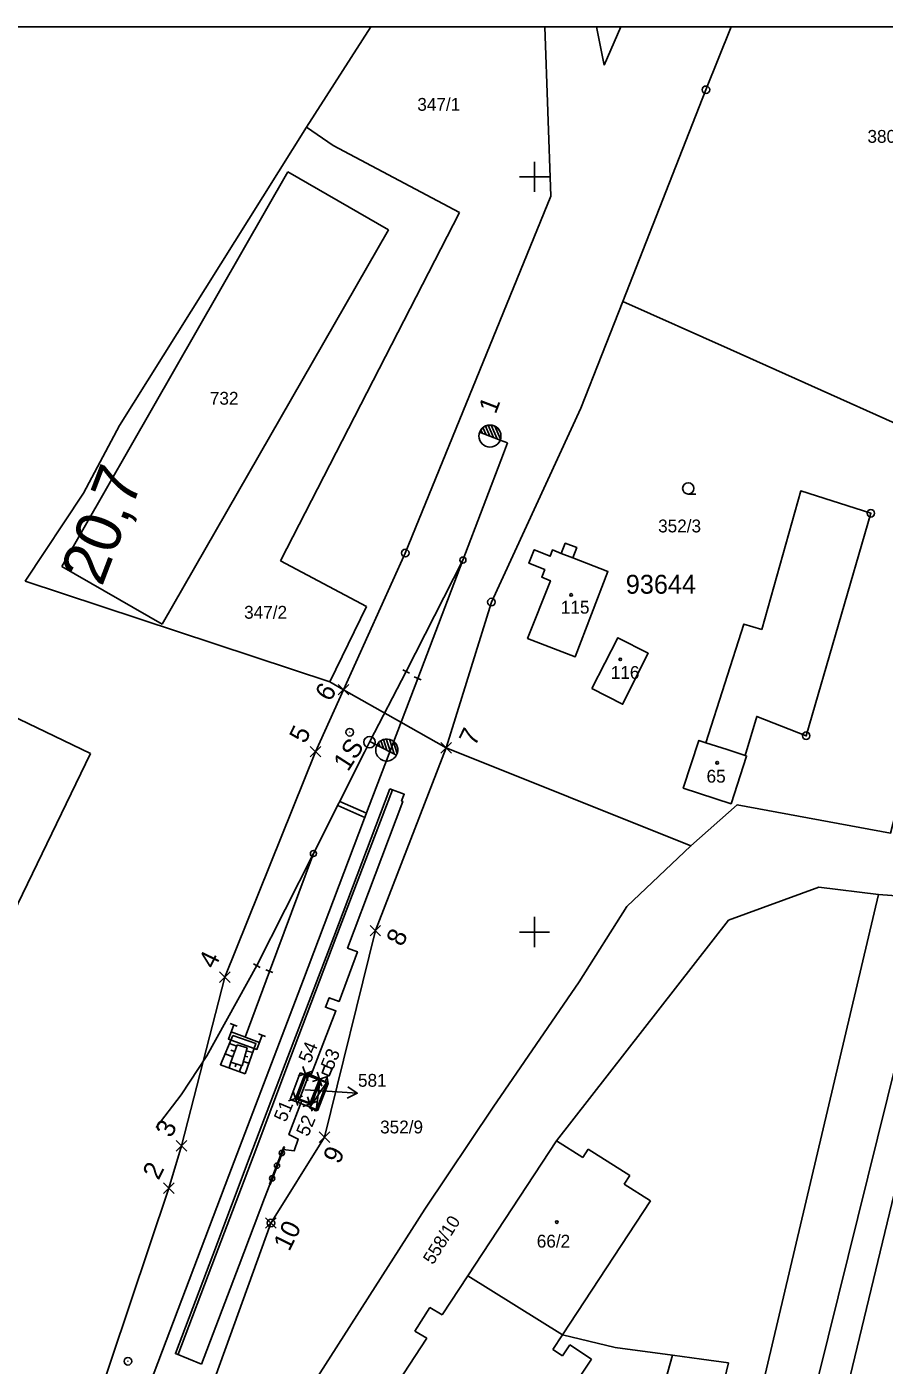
# Model space of a CAD drawing. Extents: x -778045 to -768365, y -1202571 to -1202059.
# Drawn here: x -777867.3 to -777753.6, y -1202457.4 to -1202280.1 of the extents above; entities that cross this region are included whole.
import ezdxf

# ---------------------------------------------------------------- set-up
doc = ezdxf.new("R2010")
doc.units = 0
for name, color, linetype in [('BPEJ', 7, 'Continuous'), ('GD_Demolice', 7, 'Continuous'), ('GD_Nový stav', 7, 'Continuous'), ('GD_Starý stav', 7, 'Continuous'), ('Groma (60)', 7, 'Continuous'), ('Katastr_HRANICE DRÁHY', 7, 'Continuous'), ('Katastr_Hranice katastrální', 7, 'Continuous'), ('Katastr_Hranice parcel', 7, 'Continuous'), ('Katastr_Parcelní čísla', 7, 'Continuous'), ('Katastr_Slučkované čáry', 7, 'Continuous'), ('Katastr_Značky kultur', 7, 'Continuous'), ('Vrstva 7', 7, 'Continuous'), ('čtvercová síť', 7, 'Continuous')]:
    doc.layers.add(name, color=color, linetype=linetype)

# ---------------------------------------------------------------- blocks, each defined once
blk = doc.blocks.new('POINT_DISPLAY')
for p, q in [((-0.7, -0.7), (0.7, 0.7)), ((-0.7, 0.7), (0.7, -0.7))]:
    blk.add_line(p, q)
blk = doc.blocks.new('C691')
at = {"layer": 'čtvercová síť'}
for p, q in [((0, 0.5), (0, -0.5)), ((-0.5, 0), (0.5, 0))]:
    blk.add_line(p, q, dxfattribs=at)

msp = doc.modelspace()

# ---------------------------------------------------------------- linework, layer by layer
at = {"layer": 'BPEJ'}
for points in [[(-777788.3, -1202316.49), (-777774.01, -1202322.88), (-777740.14, -1202338.03), (-777752.8, -1202386.89), (-777773.14, -1202383.15), (-777779.27, -1202388.61), (-777811.7, -1202375.6), (-777805.7, -1202356.3), (-777793.87, -1202330.63), (-777788.3, -1202316.49)], [(-777769.85, -1202359.94), (-777764.72, -1202341.59), (-777755.42, -1202344.55), (-777763.99, -1202374), (-777770.53, -1202371.45), (-777772.08, -1202376.64), (-777771.88, -1202376.7), (-777773.95, -1202383.02), (-777780.27, -1202380.95), (-777778.2, -1202374.63), (-777777.29, -1202374.93), (-777772.26, -1202359.22), (-777769.85, -1202359.94)], [(-777796.44, -1202349.87), (-777795.91, -1202348.51), (-777794.39, -1202349.09), (-777794.91, -1202350.46), (-777790.27, -1202352.24), (-777794.6, -1202363.54), (-777800.91, -1202361.12), (-777797.88, -1202353.49), (-777799.04, -1202353.02), (-777798.64, -1202352), (-777800.73, -1202351.17), (-777800.03, -1202349.39), (-777797.93, -1202350.23), (-777797.61, -1202349.41), (-777796.44, -1202349.87)], [(-777792.39, -1202367.77), (-777788.94, -1202361.03), (-777784.91, -1202363.08), (-777788.31, -1202369.84), (-777792.39, -1202367.77)]]:
    msp.add_lwpolyline(points, dxfattribs=at)
at = {"layer": 'Defpoints'}
msp.add_line((-777624.79, -1202280.12), (-778044.79, -1202280.12), dxfattribs=at)
at = {"layer": 'GD_Demolice'}
for points in [[(-777829.5, -1202422.72), (-777831.43, -1202422.03), (-777830.16, -1202418.71)], [(-777830.16, -1202418.71), (-777828.31, -1202419.48), (-777829.5, -1202422.72)]]:
    msp.add_lwpolyline(points, dxfattribs=at)
at = {"layer": 'GD_Nový stav'}
for p, q in [((-777831.04, -1202418.63), (-777832.39, -1202422.18)), ((-777831.04, -1202418.63), (-777829.96, -1202419.04)), ((-777827.5, -1202419.87), (-777829.8, -1202423.27)), ((-777829.77, -1202423.18), (-777828.42, -1202419.63)), ((-777828.38, -1202419.53), (-777828.92, -1202423.61)), ((-777832.39, -1202422.18), (-777831.31, -1202422.59))]:
    msp.add_line(p, q, dxfattribs=at)
for points in [[(-777827.76, -1202417.74), (-777826.82, -1202418.09), (-777827.18, -1202419.03), (-777828.11, -1202418.67)], [(-777829.96, -1202419.04), (-777827.53, -1202419.96), (-777828.88, -1202423.52), (-777831.31, -1202422.59)]]:
    msp.add_lwpolyline(points, close=True, dxfattribs=at)
for points in [[(-777829.12, -1202423.53), (-777829.16, -1202423.63), (-777828.95, -1202423.7), (-777828.69, -1202423.59), (-777827.34, -1202420.04), (-777827.47, -1202419.25)], [(-777828.42, -1202419.63), (-777828.38, -1202419.53), (-777827.5, -1202419.87), (-777827.53, -1202419.96)], [(-777827.68, -1202419.8), (-777827.36, -1202418.96)], [(-777829.77, -1202423.18), (-777829.8, -1202423.27), (-777828.92, -1202423.61), (-777828.88, -1202423.52)], [(-777833.12, -1202428.48), (-777833.22, -1202428.45), (-777835.1, -1202433.4), (-777835.01, -1202433.44), (-777833.12, -1202428.48)]]:
    msp.add_lwpolyline(points, dxfattribs=at)
for centre in [(-777833.47, -1202429.26), (-777834.11, -1202430.94), (-777834.75, -1202432.63)]:
    msp.add_circle(centre, 0.35, dxfattribs=at)
at = {"layer": 'GD_Starý stav'}
for p, q in [((-777806.9, -1202333.95), (-777807.1, -1202333.51)), ((-777806.41, -1202334.14), (-777806.82, -1202333.21)), ((-777805.91, -1202334.33), (-777806.5, -1202333.01)), ((-777805.41, -1202334.52), (-777806.14, -1202332.9)), ((-777804.92, -1202334.71), (-777805.74, -1202332.88)), ((-777804.49, -1202334.75), (-777805.26, -1202333.02)), ((-777804.52, -1202334.86), (-777803.56, -1202335.22)), ((-777809.48, -1202350.75), (-777816.98, -1202365.49)), ((-777816.98, -1202365.49), (-777809.48, -1202350.75)), ((-777816.98, -1202365.49), (-777821.8, -1202374.78)), ((-777816.54, -1202365.72), (-777817.42, -1202365.26)), ((-777814.99, -1202366.59), (-777815.92, -1202366.23)), ((-777820, -1202374.51), (-777819.54, -1202375.92)), ((-777819.63, -1202374.44), (-777819.06, -1202376.16)), ((-777819.21, -1202374.48), (-777818.58, -1202376.4)), ((-777822.51, -1202376.18), (-777829.29, -1202389.61)), ((-777822.51, -1202376.18), (-777829.29, -1202389.61)), ((-777821.8, -1202374.78), (-777822.51, -1202376.18)), ((-777821.8, -1202374.78), (-777822.51, -1202376.18)), ((-777820.87, -1202375.24), (-777821.8, -1202374.78)), ((-777820.66, -1202374.94), (-777820.5, -1202375.43)), ((-777820.35, -1202374.67), (-777820.02, -1202375.67)), ((-777818.74, -1202374.69), (-777818.18, -1202376.37)), ((-777826.07, -1202383.23), (-777822.47, -1202384.82)), ((-777825.8, -1202382.7), (-777822.26, -1202384.26)), ((-777829.29, -1202389.61), (-777836.79, -1202404.45)), ((-777829.29, -1202389.61), (-777836.79, -1202404.45)), ((-777829.29, -1202389.61), (-777835.12, -1202405.21)), ((-777829.29, -1202389.61), (-777835.12, -1202405.21)), ((-777836.35, -1202404.69), (-777837.23, -1202404.21)), ((-777835.12, -1202405.21), (-777838.32, -1202413.93)), ((-777834.65, -1202405.38), (-777835.59, -1202405.03)), ((-777839.38, -1202412.47), (-777840.32, -1202412.13)), ((-777836.44, -1202414.61), (-777840.2, -1202413.24)), ((-777835.63, -1202413.85), (-777836.57, -1202413.5)), ((-777839.45, -1202415.13), (-777840.42, -1202414.76)), ((-777839.98, -1202416.53), (-777841, -1202416.14)), ((-777839.71, -1202415.83), (-777840.21, -1202415.64)), ((-777838.38, -1202416.44), (-777837.98, -1202416.55)), ((-777838.18, -1202415.72), (-777837.33, -1202415.96)), ((-777840.22, -1202417.24), (-777840.47, -1202417.99)), ((-777839.51, -1202417.47), (-777839.64, -1202417.86)), ((-777838.8, -1202417.71), (-777839.06, -1202418.49)), ((-777838.59, -1202417.16), (-777837.83, -1202417.38))]:
    msp.add_line(p, q, dxfattribs=at)
for points in [[(-777803.56, -1202335.22), (-777804.09, -1202336.62), (-777809.48, -1202350.75), (-777815.46, -1202366.41)], [(-777815.46, -1202366.41), (-777809.48, -1202350.75), (-777804.09, -1202336.62), (-777803.56, -1202335.22)], [(-777804.52, -1202334.86), (-777807.26, -1202333.81)], [(-777804.52, -1202334.86), (-777804.52, -1202334.86)], [(-777865.08, -1202504.23), (-777861.67, -1202489.74), (-777857.48, -1202477.13), (-777850.38, -1202458.32), (-777840.49, -1202432.25), (-777830.62, -1202406.28), (-777821.88, -1202383.27), (-777815.46, -1202366.41)], [(-777818.26, -1202376.56), (-777820.87, -1202375.24)], [(-777818.26, -1202376.56), (-777818.26, -1202376.56)], [(-777844.11, -1202457.24), (-777847.57, -1202455.83), (-777842.63, -1202442.78), (-777837.65, -1202429.62), (-777832.66, -1202416.55), (-777826.6, -1202400.65), (-777819.16, -1202381.05)], [(-777847.25, -1202456.03), (-777842.26, -1202442.89), (-777837.28, -1202429.79), (-777832.33, -1202416.64), (-777826.31, -1202400.77), (-777818.81, -1202381.19), (-777818.81, -1202381.2)], [(-777844.11, -1202457.24), (-777839.11, -1202444.1), (-777835.76, -1202435.24), (-777834.05, -1202430.85), (-777833.28, -1202428.8), (-777831.86, -1202428.99), (-777831.3, -1202427.43), (-777832.54, -1202426.83), (-777830.84, -1202422.31), (-777831.43, -1202422.03), (-777830.16, -1202418.71), (-777829.52, -1202418.79), (-777826.31, -1202410.46), (-777827.69, -1202409.96), (-777827.2, -1202408.71), (-777825.88, -1202409.2), (-777823.46, -1202402.62), (-777824.77, -1202402.13), (-777817.44, -1202382.7), (-777817.6, -1202382.63), (-777817.25, -1202381.75), (-777819.16, -1202381.05)], [(-777836.79, -1202404.45), (-777843.41, -1202416.39), (-777846.83, -1202421.54)], [(-777839.85, -1202412.3), (-777840.54, -1202414.18), (-777836.78, -1202415.55), (-777836.1, -1202413.68)], [(-777838.32, -1202418.76), (-777841.61, -1202417.58), (-777839.97, -1202413.69)], [(-777838.75, -1202417.73), (-777840.24, -1202417.23), (-777839.38, -1202414.96)], [(-777839.97, -1202413.69), (-777836.9, -1202414.75), (-777838.32, -1202418.76)], [(-777839.38, -1202414.96), (-777838.07, -1202415.32), (-777838.75, -1202417.73)], [(-777850.13, -1202425.87), (-777846.83, -1202421.54)]]:
    msp.add_lwpolyline(points, dxfattribs=at)
for centre, radius in [((-777805.9, -1202334.33), 1.46), ((-777809.48, -1202350.75), 0.4), ((-777829.29, -1202389.61), 0.4)]:
    msp.add_circle(centre, radius, dxfattribs=at)
for centre, start, end in [((-777805.89, -1202334.34), 339.1309, 159.0918), ((-777819.57, -1202375.9), 333.368, 153.3289), ((-777819.57, -1202375.9), 153.2834, 333.7529)]:
    msp.add_arc(centre, 1.46, start, end, dxfattribs=at)
at = {"layer": 'Katastr_HRANICE DRÁHY'}
for points in [[(-777798.62, -1202280.12), (-777797.84, -1202302.55)], [(-777791.78, -1202280.12), (-777790.77, -1202285.22)], [(-777790.77, -1202285.22), (-777788.57, -1202280.12)], [(-777777.27, -1202288.47), (-777773.95, -1202280.12)], [(-777788.3, -1202316.49), (-777777.27, -1202288.47)], [(-777817.11, -1202349.82), (-777797.84, -1202302.55)], [(-777788.3, -1202316.49), (-777793.87, -1202330.63)], [(-777805.7, -1202356.3), (-777793.87, -1202330.63)], [(-777817.11, -1202349.82), (-777825.29, -1202367.91)], [(-777805.7, -1202356.3), (-777811.7, -1202375.6)], [(-777825.29, -1202367.91), (-777829.01, -1202376.12)], [(-777841.03, -1202405.98), (-777829.01, -1202376.12)], [(-777811.7, -1202375.6), (-777821.08, -1202399.82)], [(-777821.08, -1202399.82), (-777827.81, -1202427.16)], [(-777846.76, -1202428.33), (-777841.03, -1202405.98)], [(-777827.81, -1202427.16), (-777834.92, -1202438.54)], [(-777848.44, -1202433.92), (-777846.76, -1202428.33)], [(-777863.81, -1202479.74), (-777848.44, -1202433.92)], [(-777834.92, -1202438.54), (-777859.87, -1202507.59)]]:
    msp.add_lwpolyline(points, dxfattribs=at)
at = {"layer": 'Katastr_Hranice katastrální'}
for points in [[(-777830.2, -1202293.41), (-777821.68, -1202280.12)], [(-777854.99, -1202332.94), (-777830.2, -1202293.41)], [(-777859.77, -1202341.9), (-777854.99, -1202332.94)], [(-777867.47, -1202353.53), (-777859.77, -1202341.9)]]:
    msp.add_lwpolyline(points, dxfattribs=at)
at = {"layer": 'Katastr_Hranice parcel'}
msp.add_line((-777750.49, -1202426.97), (-777772.39, -1202517.89), dxfattribs=at)
for points in [[(-777830.2, -1202293.41), (-777826.67, -1202295.84)], [(-777826.67, -1202295.84), (-777809.94, -1202304.72)], [(-777832.67, -1202299.35), (-777862.62, -1202351.59)], [(-777819.32, -1202307.02), (-777832.67, -1202299.35)], [(-777809.94, -1202304.72), (-777833.64, -1202350.84)], [(-777849.34, -1202359.23), (-777819.32, -1202307.02)], [(-777788.3, -1202316.49), (-777774.01, -1202322.88)], [(-777774.01, -1202322.88), (-777740.14, -1202338.03)], [(-777769.85, -1202359.94), (-777764.72, -1202341.59)], [(-777755.42, -1202344.55), (-777764.72, -1202341.59)], [(-777755.42, -1202344.55), (-777763.99, -1202374)], [(-777800.03, -1202349.39), (-777800.73, -1202351.17)], [(-777797.93, -1202350.23), (-777800.03, -1202349.39)], [(-777797.61, -1202349.41), (-777797.93, -1202350.23)], [(-777796.44, -1202349.87), (-777797.61, -1202349.41)], [(-777795.91, -1202348.51), (-777796.44, -1202349.87)], [(-777794.39, -1202349.09), (-777795.91, -1202348.51)], [(-777794.91, -1202350.46), (-777794.39, -1202349.09)], [(-777833.64, -1202350.84), (-777822.24, -1202356.89)], [(-777800.73, -1202351.17), (-777798.64, -1202352)], [(-777790.27, -1202352.24), (-777794.91, -1202350.46)], [(-777862.62, -1202351.59), (-777849.34, -1202359.23)], [(-777798.64, -1202352), (-777799.04, -1202353.02)], [(-777799.04, -1202353.02), (-777797.88, -1202353.49)], [(-777794.6, -1202363.54), (-777790.27, -1202352.24)], [(-777827.09, -1202366.89), (-777867.47, -1202353.53)], [(-777797.88, -1202353.49), (-777800.91, -1202361.12)], [(-777822.24, -1202356.89), (-777827.09, -1202366.89)], [(-777777.29, -1202374.93), (-777772.26, -1202359.22)], [(-777769.85, -1202359.94), (-777772.26, -1202359.22)], [(-777794.6, -1202363.54), (-777800.91, -1202361.12)], [(-777792.39, -1202367.77), (-777788.94, -1202361.03)], [(-777788.94, -1202361.03), (-777784.91, -1202363.08)], [(-777784.91, -1202363.08), (-777788.31, -1202369.84)], [(-777825.29, -1202367.91), (-777827.09, -1202366.89)], [(-777825.29, -1202367.91), (-777817.69, -1202372.21)], [(-777788.31, -1202369.84), (-777792.39, -1202367.77)], [(-777858.82, -1202376.38), (-777873.08, -1202369.51)], [(-777817.69, -1202372.21), (-777811.7, -1202375.6)], [(-777770.53, -1202371.45), (-777772.08, -1202376.64)], [(-777770.53, -1202371.45), (-777763.99, -1202374)], [(-777811.7, -1202375.6), (-777779.27, -1202388.61)], [(-777780.27, -1202380.95), (-777778.2, -1202374.63)], [(-777778.2, -1202374.63), (-777777.29, -1202374.93)], [(-777882.63, -1202425.49), (-777858.82, -1202376.38)], [(-777771.88, -1202376.7), (-777773.95, -1202383.02)], [(-777772.08, -1202376.64), (-777771.88, -1202376.7)], [(-777773.95, -1202383.02), (-777780.27, -1202380.95)], [(-777773.14, -1202383.15), (-777779.27, -1202388.61)], [(-777752.8, -1202386.89), (-777773.14, -1202383.15)], [(-777779.27, -1202388.61), (-777787.77, -1202396.63)], [(-777746.67, -1202395.6), (-777776.75, -1202516.88)], [(-777754.4, -1202395.04), (-777775.07, -1202482.53)], [(-777762.31, -1202394.08), (-777774.3, -1202398.44)], [(-777754.4, -1202395.04), (-777762.31, -1202394.08)], [(-777754.4, -1202395.04), (-777746.67, -1202395.6)], [(-777787.77, -1202396.63), (-777794.06, -1202406.58)], [(-777774.3, -1202398.44), (-777797.09, -1202427.66)], [(-777794.06, -1202406.58), (-777805.47, -1202423.21)], [(-777830.36, -1202418.75), (-777831.65, -1202422.04)], [(-777828.47, -1202419.49), (-777830.36, -1202418.75)], [(-777829.76, -1202422.77), (-777828.47, -1202419.49)], [(-777831.65, -1202422.04), (-777829.76, -1202422.77)], [(-777805.47, -1202423.21), (-777814.54, -1202436.71)], [(-777808.84, -1202445.53), (-777797.09, -1202427.66)], [(-777797.09, -1202427.66), (-777793.6, -1202429.88)], [(-777793.6, -1202429.88), (-777792.87, -1202428.75)], [(-777792.87, -1202428.75), (-777787.37, -1202432.25)], [(-777787.37, -1202432.25), (-777788.1, -1202433.39)], [(-777788.1, -1202433.39), (-777784.62, -1202435.6)], [(-777784.62, -1202435.6), (-777796.28, -1202453.34)], [(-777814.54, -1202436.71), (-777859.87, -1202507.59)], [(-777812.23, -1202450.69), (-777808.84, -1202445.53)], [(-777808.84, -1202445.53), (-777796.28, -1202453.34)], [(-777815.85, -1202452.86), (-777813.84, -1202449.71)], [(-777813.84, -1202449.71), (-777812.23, -1202450.69)], [(-777820.46, -1202463.21), (-777814.26, -1202453.78)], [(-777814.26, -1202453.78), (-777815.85, -1202452.86)], [(-777796.28, -1202453.34), (-777789.32, -1202455.02)], [(-777789.32, -1202455.02), (-777781.7, -1202456.05)], [(-777787.74, -1202477.6), (-777781.7, -1202456.05)], [(-777781.7, -1202456.05), (-777777.84, -1202456.57)], [(-777777.84, -1202456.57), (-777774.28, -1202457.03)], [(-777774.28, -1202457.03), (-777777.66, -1202471)]]:
    msp.add_lwpolyline(points, dxfattribs=at)
at = {"layer": 'Katastr_Parcelní čísla'}
for p, q in [((-777824.72, -1202420.52), (-777823.47, -1202421.35)), ((-777830.41, -1202420.91), (-777827.46, -1202421.09))]:
    msp.add_line(p, q, dxfattribs=at)
msp.add_lwpolyline([(-777827.46, -1202421.09), (-777823.47, -1202421.35), (-777824.82, -1202422.01)], dxfattribs=at)
at = {"layer": 'Katastr_Slučkované čáry'}
for points in [[(-777796.44, -1202349.87), (-777794.91, -1202350.46)], [(-777777.29, -1202374.93), (-777774.48, -1202375.85)], [(-777772.08, -1202376.64), (-777774.48, -1202375.85)], [(-777796.28, -1202453.34), (-777797.57, -1202455.28)], [(-777797.57, -1202455.28), (-777796.28, -1202456.14)], [(-777796.28, -1202456.14), (-777795.29, -1202454.67)], [(-777795.29, -1202454.67), (-777792.45, -1202456.55)], [(-777792.45, -1202456.55), (-777795.78, -1202461.59)]]:
    msp.add_lwpolyline(points, dxfattribs=at)
at = {"layer": 'Katastr_Značky kultur'}
for p, q in [((-777777.32, -1202288.47), (-777777.22, -1202288.47)), ((-777779.61, -1202342.01), (-777778.61, -1202342.01)), ((-777755.47, -1202344.55), (-777755.37, -1202344.55)), ((-777817.16, -1202349.82), (-777817.06, -1202349.82)), ((-777805.75, -1202356.3), (-777805.65, -1202356.3)), ((-777764.04, -1202374), (-777763.94, -1202374)), ((-777834.97, -1202438.54), (-777834.87, -1202438.54))]:
    msp.add_line(p, q, dxfattribs=at)
for centre, radius in [((-777777.27, -1202288.47), 0.499), ((-777779.61, -1202341.26), 0.75), ((-777755.42, -1202344.55), 0.499), ((-777817.11, -1202349.82), 0.499), ((-777805.7, -1202356.3), 0.499), ((-777795.14, -1202355.37), 0.175), ((-777788.62, -1202363.89), 0.175), ((-777763.99, -1202374), 0.499), ((-777775.78, -1202377.59), 0.175), ((-777834.92, -1202438.54), 0.499), ((-777797.03, -1202438.41), 0.175)]:
    msp.add_circle(centre, radius, dxfattribs=at)
at = {"layer": 'Vrstva 7'}
for p, q in [((-777824.44, -1202373.51), (-777824.49, -1202373.59)), ((-777853.89, -1202456.89), (-777853.86, -1202456.8))]:
    msp.add_line(p, q, dxfattribs=at)
for centre, radius in [((-777824.47, -1202373.55), 0.5), ((-777821.85, -1202374.86), 0.75), ((-777853.87, -1202456.85), 0.5)]:
    msp.add_circle(centre, radius, dxfattribs=at)

# ---------------------------------------------------------------- block references
at = {"layer": 'Groma (60)'}
for p, rotation in [((-777825.29, -1202367.91), 180), ((-777829.01, -1202376.12), 180), ((-777811.7, -1202375.6), 180), ((-777821.08, -1202399.82), 180), ((-777841.03, -1202405.98), 180), ((-777830.36, -1202418.75), 63.74607776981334), ((-777828.47, -1202419.49), 63.74607776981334), ((-777831.65, -1202422.04), 63.74607776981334), ((-777829.76, -1202422.77), 63.74607776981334), ((-777846.76, -1202428.33), 180), ((-777827.81, -1202427.16), 180), ((-777848.44, -1202433.92), 180), ((-777834.92, -1202438.54), 180)]:
    msp.add_blockref('POINT_DISPLAY', p, dxfattribs=dict(at, rotation=rotation))
at = {"layer": 'čtvercová síť', "xscale": 4, "yscale": 4}
for p in [(-777800, -1202300), (-777800, -1202400)]:
    msp.add_blockref('C691', p, dxfattribs=at)

# ---------------------------------------------------------------- texts
at = {"layer": 'BPEJ'}
msp.add_text('93644', height=2.5, dxfattribs=at).set_placement((-777787.89, -1202355.2))
at = {"layer": 'GD_Starý stav'}
for s, rotation, p in [('1', 69.1114, (-777805.14, -1202331.51)), ('1S', 57.2611, (-777824.71, -1202378.86))]:
    msp.add_text(s, height=2.5, rotation=rotation, dxfattribs=at).set_placement(p)
at = {"layer": 'Groma (60)'}
for s, height, rotation, p in [('6', 2.5, 58.7659, (-777827.09, -1202369.61)), ('5', 2.5, 63.6236, (-777830.38, -1202375.16)), ('7', 2.5, 63.6236, (-777807.87, -1202375.5)), ('8', 2.5, 63.6236, (-777817.53, -1202402.05)), ('4', 2.5, 63.6236, (-777842.4, -1202405.02)), ('54', 1.8, 67.297, (-777829.69, -1202417.48)), ('53', 1.8, 67.297, (-777826.74, -1202418.4)), ('51', 1.8, 67.297, (-777832.95, -1202425.28)), ('3', 2.5, 63.6236, (-777848.13, -1202427.37)), ('52', 1.8, 67.297, (-777829.99, -1202427.2)), ('9', 2.5, 63.6236, (-777825.89, -1202430.86)), ('2', 2.5, 63.6236, (-777849.81, -1202432.96)), ('10', 2.5, 63.6236, (-777832.48, -1202442.39))]:
    msp.add_text(s, height=height, rotation=rotation, dxfattribs=at).set_placement(p)
at = {"layer": 'Katastr_Parcelní čísla'}
for s, p in [('347/1', (-777815.52, -1202291.25)), ('380/3', (-777755.87, -1202295.49)), ('732', (-777843.01, -1202330.17)), ('352/3', (-777783.61, -1202347.08)), ('347/2', (-777838.47, -1202358.51)), ('115', (-777796.5, -1202357.84)), ('116', (-777789.88, -1202366.48)), ('65', (-777777.19, -1202380.22)), ('581', (-777823.38, -1202420.49)), ('352/9', (-777820.45, -1202426.67)), ('66/2', (-777799.69, -1202441.79))]:
    msp.add_text(s, height=1.7, dxfattribs=at).set_placement(p)
msp.add_text('558/10', height=1.7, rotation=57.8531, dxfattribs=at).set_placement((-777813.44, -1202444.15))
at = {"layer": 'Vrstva 7'}
msp.add_text('20,7', height=6, rotation=69.1195, dxfattribs=at).set_placement((-777857.32, -1202354.38))

doc.saveas('drawing.dxf')
